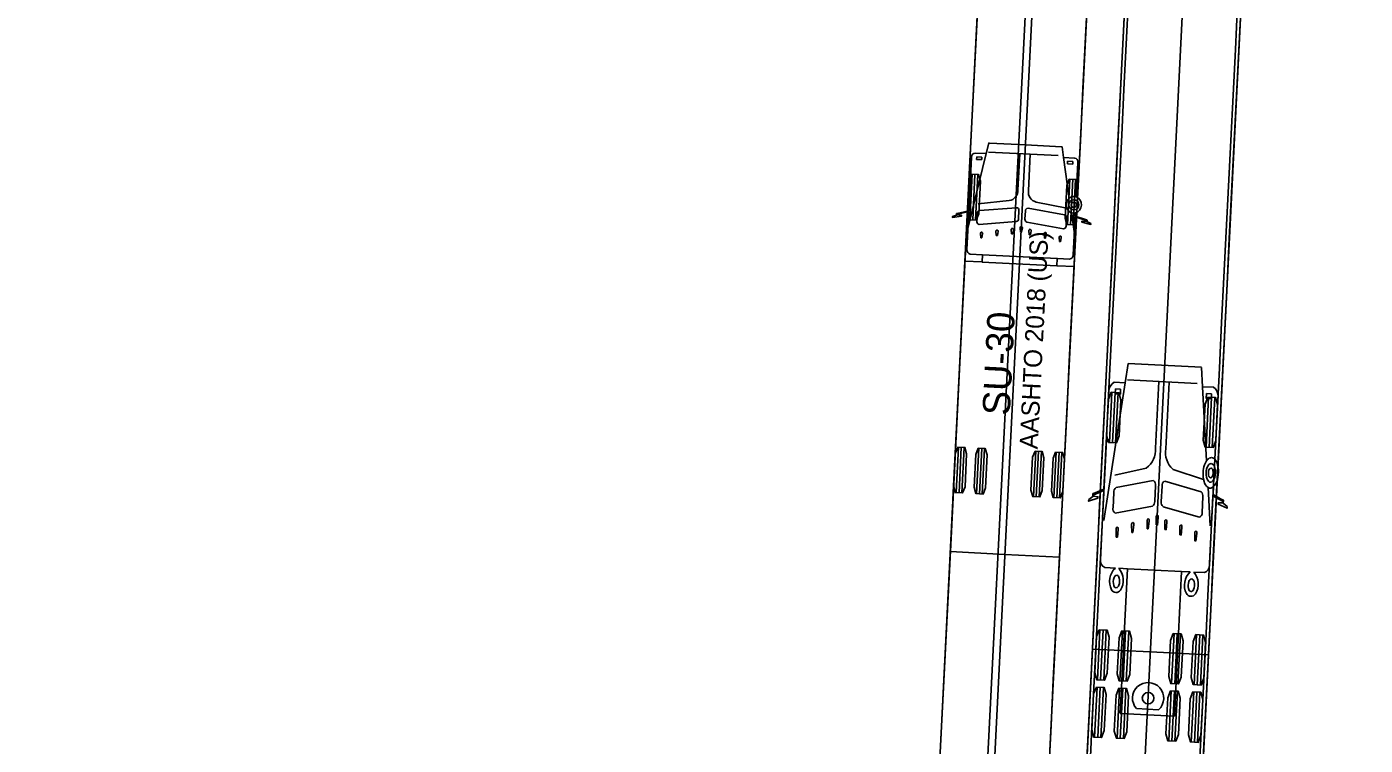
# Model space of a CAD drawing. Extents: x 260275 to 261282, y 610916 to 614143.
# Drawn here: x 260986.2 to 261084.3, y 612318.4 to 612371 of the extents above; entities that cross this region are included whole.
import ezdxf

# ---------------------------------------------------------------- set-up
doc = ezdxf.new("R2010")
doc.units = 0
doc.layers.add('GE_X_Alignment', color=7, linetype='Continuous')
doc.layers.add('TopoDOT_Transients', color=7, linetype='Continuous')

msp = doc.modelspace()

# ---------------------------------------------------------------- linework, layer by layer
at = {"layer": 'GE_X_Alignment'}
msp.add_line((260986.249, 610915.954), (261148.276, 614142.838), dxfattribs=at)
at = {"layer": 'TopoDOT_Transients'}
for p, q in [((261059.045, 612136.423), (261081.046, 612574.591)), ((261048.059, 612136.974), (261068.197, 612538.052)), ((261055.162, 612356.208), (261056.503, 612361.676)), ((261061.757, 612361.535), (261056.658, 612361.791)), ((261058.958, 612361.676), (261058.824, 612359.011)), ((261059.723, 612361.637), (261059.589, 612358.972)), ((261055.791, 612361.255), (261055.801, 612361.449)), ((261056.17, 612361.236), (261055.791, 612361.255)), ((261055.801, 612361.449), (261056.179, 612361.43)), ((261056.179, 612361.43), (261056.17, 612361.236)), ((261062.584, 612358.426), (261062.166, 612361.391)), ((261062.463, 612361.115), (261062.453, 612360.921)), ((261062.453, 612360.921), (261062.831, 612360.902)), ((261062.841, 612361.096), (261062.463, 612361.115)), ((261062.831, 612360.902), (261062.841, 612361.096)), ((261063.088, 612358.516), (261063.214, 612361.035)), ((261055.469, 612360.17), (261055.302, 612356.841)), ((261055.677, 612360.16), (261055.51, 612356.831)), ((261055.885, 612360.15), (261055.718, 612356.82)), ((261062.627, 612359.811), (261062.46, 612356.482)), ((261062.835, 612359.801), (261062.668, 612356.472)), ((261063.043, 612359.79), (261062.876, 612356.461)), ((261058.186, 612358.235), (261055.907, 612358.004)), ((261056.014, 612357.505), (261058.723, 612357.721)), ((261062.234, 612357.192), (261059.561, 612357.679)), ((261060.146, 612358.136), (261062.402, 612357.676)), ((261055.822, 612356.695), (261055.853, 612357.311)), ((261058.702, 612356.7), (261055.993, 612356.484)), ((261058.894, 612357.51), (261058.863, 612356.894)), ((261059.369, 612357.486), (261059.338, 612356.87)), ((261059.479, 612356.661), (261062.153, 612356.174)), ((261062.344, 612356.367), (261062.375, 612356.983)), ((261062.952, 612355.817), (261062.736, 612357.351)), ((261056.105, 612355.524), (261056.084, 612355.825)), ((261056.238, 612355.818), (261056.187, 612355.52)), ((261057.231, 612355.678), (261057.21, 612355.993)), ((261057.314, 612355.674), (261057.231, 612355.678)), ((261057.364, 612355.986), (261057.314, 612355.674)), ((261058.356, 612355.804), (261058.335, 612356.106)), ((261058.439, 612355.8), (261058.356, 612355.804)), ((261058.49, 612356.098), (261058.439, 612355.8)), ((261059.012, 612355.94), (261058.991, 612356.241)), ((261059.094, 612355.936), (261059.012, 612355.94)), ((261059.145, 612356.233), (261059.094, 612355.936)), ((261059.651, 612355.739), (261059.63, 612356.041)), ((261059.733, 612355.735), (261059.651, 612355.739)), ((261059.784, 612356.033), (261059.733, 612355.735)), ((261060.758, 612355.501), (261060.737, 612355.802)), ((261060.891, 612355.795), (261060.84, 612355.497)), ((261056.187, 612355.52), (261056.105, 612355.524)), ((261060.84, 612355.497), (261060.758, 612355.501)), ((261061.863, 612355.235), (261061.842, 612355.536)), ((261061.945, 612355.231), (261061.863, 612355.235)), ((261061.996, 612355.529), (261061.945, 612355.231)), ((261061.679, 612353.471), (261056.194, 612353.746)), ((261061.705, 612354.001), (261056.22, 612354.277)), ((261072.259, 612346.049), (261066.895, 612346.318)), ((261065.102, 612334.832), (261066.674, 612344.901)), ((261071.934, 612344.862), (261066.835, 612345.118)), ((261069.135, 612345.003), (261068.889, 612340.117)), ((261069.899, 612344.964), (261069.654, 612340.079)), ((261065.703, 612344.208), (261065.519, 612340.546)), ((261065.931, 612344.197), (261065.748, 612340.535)), ((261065.944, 612344.101), (261065.962, 612344.456)), ((261066.322, 612344.082), (261065.944, 612344.101)), ((261065.962, 612344.456), (261066.34, 612344.437)), ((261066.16, 612344.185), (261065.976, 612340.523)), ((261066.34, 612344.437), (261066.322, 612344.082)), ((261072.633, 612339.203), (261072.337, 612344.616)), ((261072.624, 612344.122), (261072.606, 612343.766)), ((261073.002, 612344.103), (261072.624, 612344.122)), ((261072.984, 612343.747), (261073.002, 612344.103)), ((261073.237, 612339.306), (261073.473, 612344.001)), ((261072.777, 612343.853), (261072.593, 612340.191)), ((261072.606, 612343.766), (261072.984, 612343.747)), ((261073.006, 612343.842), (261072.822, 612340.18)), ((261073.235, 612343.83), (261073.051, 612340.168)), ((261054.466, 612340.196), (261054.299, 612336.867)), ((261054.674, 612340.185), (261054.507, 612336.856)), ((261054.883, 612340.175), (261054.715, 612336.846)), ((261055.964, 612340.12), (261055.797, 612336.791)), ((261056.173, 612340.11), (261056.005, 612336.781)), ((261056.381, 612340.1), (261056.213, 612336.77)), ((261060.126, 612339.911), (261059.959, 612336.582)), ((261060.334, 612339.901), (261060.167, 612336.572)), ((261060.542, 612339.891), (261060.375, 612336.561)), ((261061.624, 612339.836), (261061.457, 612336.507)), ((261061.832, 612339.826), (261061.665, 612336.497)), ((261062.04, 612339.815), (261061.873, 612336.486)), ((261068.217, 612338.67), (261065.924, 612338.151)), ((261070.178, 612338.571), (261072.419, 612337.822)), ((261066.011, 612337.242), (261068.734, 612337.751)), ((261068.897, 612337.372), (261068.84, 612336.243)), ((261069.372, 612337.348), (261069.315, 612336.219)), ((261072.23, 612336.93), (261069.572, 612337.709)), ((261072.893, 612334.441), (261072.74, 612337.241)), ((261064.33, 612336.6), (261064.309, 612336.585)), ((261064.356, 612336.598), (261064.33, 612336.6)), ((261065.784, 612335.751), (261065.841, 612336.88)), ((261072.307, 612335.423), (261072.363, 612336.552)), ((261073.812, 612336.123), (261073.838, 612336.123)), ((261073.838, 612336.123), (261073.858, 612336.105)), ((261068.67, 612335.88), (261065.947, 612335.372)), ((261068.949, 612334.502), (261068.941, 612335.053)), ((261069.448, 612335.841), (261072.107, 612335.062)), ((261066.019, 612333.619), (261066.011, 612334.17)), ((261066.165, 612334.162), (261066.101, 612333.615)), ((261067.154, 612333.948), (261067.146, 612334.524)), ((261067.3, 612334.517), (261067.236, 612333.944)), ((261068.287, 612334.226), (261068.278, 612334.777)), ((261068.369, 612334.222), (261068.287, 612334.226)), ((261068.432, 612334.769), (261068.369, 612334.222)), ((261069.032, 612334.498), (261068.949, 612334.502)), ((261069.095, 612335.045), (261069.032, 612334.498)), ((261069.581, 612334.161), (261069.573, 612334.712)), ((261069.664, 612334.157), (261069.581, 612334.161)), ((261069.727, 612334.704), (261069.664, 612334.157)), ((261070.68, 612333.771), (261070.672, 612334.322)), ((261070.826, 612334.314), (261070.763, 612333.767)), ((261066.101, 612333.615), (261066.019, 612333.619)), ((261067.236, 612333.944), (261067.154, 612333.948)), ((261070.763, 612333.767), (261070.68, 612333.771)), ((261071.777, 612333.33), (261071.769, 612333.881)), ((261071.859, 612333.326), (261071.777, 612333.33)), ((261071.923, 612333.873), (261071.859, 612333.326)), ((261065.18, 612331.385), (261065.954, 612331.346)), ((261070.809, 612331.103), (261066.841, 612331.302)), ((261071.696, 612331.058), (261072.471, 612331.019)), ((261064.83, 612326.83), (261064.646, 612323.168)), ((261065.059, 612326.819), (261064.875, 612323.157)), ((261065.288, 612326.807), (261065.104, 612323.145)), ((261066.478, 612326.748), (261066.294, 612323.086)), ((261066.707, 612326.736), (261066.523, 612323.074)), ((261066.936, 612326.725), (261066.752, 612323.063)), ((261070.256, 612326.558), (261070.073, 612322.896)), ((261070.485, 612326.546), (261070.301, 612322.884)), ((261070.714, 612326.535), (261070.53, 612322.873)), ((261071.904, 612326.475), (261071.721, 612322.813)), ((261072.133, 612326.464), (261071.949, 612322.802)), ((261072.362, 612326.452), (261072.178, 612322.79)), ((261064.619, 612322.636), (261064.435, 612318.974)), ((261064.848, 612322.624), (261064.664, 612318.962)), ((261065.077, 612322.613), (261064.893, 612318.951)), ((261066.267, 612322.553), (261066.083, 612318.891)), ((261066.496, 612322.541), (261066.312, 612318.879)), ((261066.725, 612322.53), (261066.541, 612318.868)), ((261070.046, 612322.363), (261069.862, 612318.701)), ((261070.275, 612322.352), (261070.091, 612318.69)), ((261070.504, 612322.34), (261070.32, 612318.678)), ((261071.694, 612322.28), (261071.51, 612318.618)), ((261071.923, 612322.269), (261071.739, 612318.607)), ((261072.152, 612322.257), (261071.968, 612318.595)), ((261067.507, 612321.059), (261069.121, 612320.978))]:
    msp.add_line(p, q, dxfattribs=at)
for points in [[(261051.548, 612071.863), (261074.206, 612523.277)], [(261082.631, 612521.243), (261060.03, 612071.291)], [(261042.767, 612111.356), (261063.016, 612514.614)], [(261070.923, 612512.551), (261050.75, 612110.806), (261042.76, 612111.207), (261042.767, 612111.356), (261042.767, 612111.356)], [(261053.088, 612316.907), (261053.256, 612320.235), (261053.423, 612323.564), (261053.59, 612326.892), (261053.757, 612330.22), (261053.924, 612333.549), (261054.091, 612336.877), (261054.258, 612340.206), (261054.425, 612343.534), (261054.593, 612346.863), (261054.76, 612350.191), (261054.927, 612353.52), (261055.094, 612356.848), (261055.261, 612360.176), (261055.428, 612363.505), (261055.595, 612366.833), (261055.762, 612370.162), (261055.93, 612373.49)], [(261053.089, 612316.911), (261053.256, 612320.239), (261053.423, 612323.568), (261053.59, 612326.896), (261053.757, 612330.225), (261053.924, 612333.553), (261054.091, 612336.881), (261054.258, 612340.21), (261054.426, 612343.538), (261054.593, 612346.867), (261054.76, 612350.195), (261054.927, 612353.524), (261055.094, 612356.852), (261055.261, 612360.181), (261055.428, 612363.509), (261055.596, 612366.837), (261055.763, 612370.166), (261055.93, 612373.494)], [(261061.078, 612316.505), (261061.245, 612319.834), (261061.413, 612323.162), (261061.58, 612326.491), (261061.747, 612329.819), (261061.914, 612333.148), (261062.081, 612336.476), (261062.248, 612339.805), (261062.415, 612343.133), (261062.582, 612346.461), (261062.75, 612349.79), (261062.917, 612353.118), (261063.084, 612356.447), (261063.251, 612359.775), (261063.418, 612363.104), (261063.585, 612366.432), (261063.752, 612369.761), (261063.919, 612373.089)], [(261061.079, 612316.51), (261061.246, 612319.838), (261061.413, 612323.166), (261061.58, 612326.495), (261061.747, 612329.823), (261061.914, 612333.152), (261062.081, 612336.48), (261062.248, 612339.809), (261062.416, 612343.137), (261062.583, 612346.466), (261062.75, 612349.794), (261062.917, 612353.123), (261063.084, 612356.451), (261063.251, 612359.779), (261063.418, 612363.108), (261063.585, 612366.436), (261063.753, 612369.765), (261063.92, 612373.093)], [(261063.803, 612315.939), (261063.971, 612319.268), (261064.138, 612322.598), (261064.305, 612325.928), (261064.472, 612329.257), (261064.639, 612332.587), (261064.806, 612335.916), (261064.974, 612339.246), (261065.141, 612342.575), (261065.308, 612345.905), (261065.475, 612349.234), (261065.642, 612352.564), (261065.81, 612355.893), (261065.977, 612359.223), (261066.144, 612362.553), (261066.311, 612365.882), (261066.478, 612369.212), (261066.645, 612372.541)], [(261064.078, 612316.418), (261064.245, 612319.748), (261064.412, 612323.078), (261064.579, 612326.407), (261064.746, 612329.737), (261064.914, 612333.066), (261065.081, 612336.396), (261065.248, 612339.725), (261065.415, 612343.055), (261065.582, 612346.384), (261065.75, 612349.714), (261065.917, 612353.043), (261066.084, 612356.373), (261066.251, 612359.703), (261066.418, 612363.032), (261066.585, 612366.362), (261066.753, 612369.691), (261066.92, 612373.021)], [(261072.068, 612316.017), (261072.235, 612319.347), (261072.402, 612322.676), (261072.569, 612326.006), (261072.736, 612329.335), (261072.904, 612332.665), (261073.071, 612335.995), (261073.238, 612339.324), (261073.405, 612342.654), (261073.572, 612345.983), (261073.739, 612349.313), (261073.907, 612352.642), (261074.074, 612355.972), (261074.241, 612359.301), (261074.408, 612362.631), (261074.575, 612365.96), (261074.743, 612369.29), (261074.91, 612372.62)], [(261072.293, 612315.513), (261072.46, 612318.842), (261072.627, 612322.172), (261072.794, 612325.501), (261072.961, 612328.831), (261073.129, 612332.16), (261073.296, 612335.49), (261073.463, 612338.819), (261073.63, 612342.149), (261073.797, 612345.479), (261073.964, 612348.808), (261074.132, 612352.138), (261074.299, 612355.467), (261074.466, 612358.797), (261074.633, 612362.126), (261074.8, 612365.456), (261074.968, 612368.785), (261075.135, 612372.115)], [(261062.976, 612361.351), (261062.17, 612361.391), (261062.165, 612361.396), (261062.056, 612362.174), (261062.014, 612362.178), (261059.373, 612362.311), (261056.733, 612362.443), (261056.691, 612362.443), (261056.504, 612361.68), (261056.499, 612361.676), (261055.692, 612361.716)], [(261055.424, 612361.426), (261055.227, 612357.498), (261055.219, 612357.487), (261054.378, 612357.302), (261054.377, 612357.303)], [(261054.333, 612357.232), (261054.329, 612357.185), (261054.329, 612357.184), (261054.028, 612357.067), (261054.025, 612357.003), (261054.028, 612357.003), (261054.69, 612357.109), (261054.693, 612357.11), (261054.696, 612357.165), (261054.693, 612357.166), (261054.376, 612357.19), (261054.376, 612357.191), (261054.379, 612357.235)], [(261054.391, 612357.254), (261054.391, 612357.254), (261055.219, 612357.433), (261055.223, 612357.42), (261055.084, 612354.65)], [(261062.874, 612354.259), (261063.013, 612357.029), (261063.018, 612357.041), (261063.824, 612356.781), (261063.824, 612356.781)], [(261063.843, 612356.827), (261063.842, 612356.827), (261063.023, 612357.095), (261063.017, 612357.107), (261063.028, 612357.335)], [(261063.834, 612356.76), (261063.832, 612356.716), (261063.832, 612356.715), (261063.514, 612356.723), (261063.512, 612356.723), (261063.509, 612356.667), (261063.512, 612356.666), (261064.16, 612356.494), (261064.163, 612356.493), (261064.166, 612356.558), (261063.878, 612356.705), (261063.878, 612356.705), (261063.88, 612356.752)], [(261055.322, 612354.322), (261056.217, 612354.277), (261056.22, 612354.273), (261056.194, 612353.747), (261056.183, 612353.747), (261054.941, 612353.809), (261053.874, 612332.549), (261057.869, 612332.348), (261061.864, 612332.148), (261062.931, 612353.408), (261061.69, 612353.47), (261061.679, 612353.471), (261061.705, 612353.998), (261061.709, 612354.001), (261062.604, 612353.956)], [(261072.259, 612346.049), (261066.895, 612346.318), (261066.674, 612344.901), (261065.86, 612344.942)], [(261073.151, 612344.575), (261072.337, 612344.616), (261072.26, 612346.037)], [(261065.483, 612344.402), (261065.118, 612337.134), (261064.361, 612336.803)], [(261064.374, 612336.716), (261064.374, 612336.716), (261065.113, 612337.035), (261064.858, 612331.96)], [(261073.827, 612336.328), (261073.108, 612336.733), (261073.137, 612337.306)], [(261064.314, 612336.672), (261064.309, 612336.585), (261064.002, 612336.359), (261063.996, 612336.239), (261064.67, 612336.463), (261064.675, 612336.566), (261064.356, 612336.598), (261064.361, 612336.68)], [(261072.848, 612331.559), (261073.103, 612336.634), (261073.806, 612336.242), (261073.806, 612336.242)], [(261073.816, 612336.205), (261073.812, 612336.123), (261073.491, 612336.123), (261073.486, 612336.02), (261074.134, 612335.73), (261074.14, 612335.85), (261073.858, 612336.105), (261073.861, 612336.192)], [(261066.211, 612331.333), (261066.841, 612331.302), (261066.309, 612320.715), (261070.278, 612320.516), (261070.809, 612331.103), (261071.439, 612331.071)], [(261070.343, 612277.129), (261070.365, 612277.127), (261072.769, 612324.997), (261068.524, 612325.21), (261064.28, 612325.423), (261061.876, 612277.554), (261061.898, 612277.553)]]:
    msp.add_lwpolyline(points, dxfattribs=at)
for points in [[(261055.418, 612360.173), (261055.937, 612360.147), (261056.07, 612359.673), (261055.95, 612357.276), (261055.77, 612356.818), (261055.251, 612356.844), (261055.118, 612357.318), (261055.238, 612359.715)], [(261062.575, 612359.814), (261063.095, 612359.788), (261063.228, 612359.314), (261063.107, 612356.917), (261062.928, 612356.458), (261062.408, 612356.485), (261062.275, 612356.958), (261062.396, 612359.355)], [(261065.646, 612344.211), (261066.217, 612344.183), (261066.363, 612343.661), (261066.231, 612341.025), (261066.033, 612340.521), (261065.462, 612340.549), (261065.316, 612341.071), (261065.448, 612343.707)], [(261072.72, 612343.856), (261073.292, 612343.827), (261073.438, 612343.306), (261073.306, 612340.669), (261073.108, 612340.165), (261072.536, 612340.194), (261072.39, 612340.715), (261072.522, 612343.352)], [(261054.415, 612340.198), (261054.934, 612340.172), (261055.067, 612339.698), (261054.947, 612337.301), (261054.767, 612336.843), (261054.248, 612336.869), (261054.115, 612337.343), (261054.235, 612339.74)], [(261055.913, 612340.123), (261056.432, 612340.097), (261056.565, 612339.623), (261056.445, 612337.226), (261056.265, 612336.768), (261055.746, 612336.794), (261055.613, 612337.268), (261055.733, 612339.665)], [(261060.074, 612339.914), (261060.594, 612339.888), (261060.727, 612339.414), (261060.606, 612337.017), (261060.426, 612336.559), (261059.907, 612336.585), (261059.774, 612337.059), (261059.894, 612339.456)], [(261061.572, 612339.839), (261062.092, 612339.813), (261062.225, 612339.339), (261062.104, 612336.942), (261061.925, 612336.484), (261061.405, 612336.51), (261061.272, 612336.984), (261061.393, 612339.381)], [(261064.773, 612326.833), (261065.345, 612326.805), (261065.491, 612326.283), (261065.359, 612323.647), (261065.161, 612323.142), (261064.589, 612323.171), (261064.443, 612323.692), (261064.575, 612326.329)], [(261066.421, 612326.75), (261066.992, 612326.722), (261067.139, 612326.2), (261067.006, 612323.564), (261066.809, 612323.06), (261066.237, 612323.088), (261066.091, 612323.61), (261066.223, 612326.246)], [(261070.2, 612326.561), (261070.771, 612326.532), (261070.917, 612326.011), (261070.785, 612323.374), (261070.587, 612322.87), (261070.016, 612322.899), (261069.869, 612323.42), (261070.002, 612326.057)], [(261071.848, 612326.478), (261072.419, 612326.449), (261072.565, 612325.928), (261072.433, 612323.291), (261072.235, 612322.787), (261071.664, 612322.816), (261071.517, 612323.337), (261071.65, 612325.974)], [(261064.563, 612322.638), (261065.134, 612322.61), (261065.28, 612322.088), (261065.148, 612319.452), (261064.95, 612318.948), (261064.379, 612318.976), (261064.232, 612319.498), (261064.365, 612322.134)], [(261066.211, 612322.556), (261066.782, 612322.527), (261066.928, 612322.006), (261066.796, 612319.369), (261066.598, 612318.865), (261066.027, 612318.894), (261065.88, 612319.415), (261066.013, 612322.052)], [(261069.989, 612322.366), (261070.56, 612322.337), (261070.707, 612321.816), (261070.574, 612319.179), (261070.377, 612318.675), (261069.805, 612318.704), (261069.659, 612319.225), (261069.791, 612321.862)], [(261071.637, 612322.283), (261072.208, 612322.255), (261072.355, 612321.733), (261072.222, 612319.097), (261072.024, 612318.593), (261071.453, 612318.621), (261071.307, 612319.143), (261071.439, 612321.779)]]:
    msp.add_lwpolyline(points, close=True, dxfattribs=at)
for centre, radius in [((261062.913, 612357.933), 0.374), ((261062.913, 612357.933), 0.193), ((261068.354, 612321.826), 0.424)]:
    msp.add_circle(centre, radius, dxfattribs=at)
for centre, radius, start, end in [((261055.705, 612361.435), 0.282, 92.67391, 181.75333), ((261062.935, 612361.072), 0.282, 352.49767, 81.5771), ((261058.051, 612358.996), 0.773, 280.01597, 1.10013), ((261060.356, 612358.88), 0.773, 173.15088, 254.23504), ((261058.712, 612357.537), 0.184, 351.66723, 86.52737), ((261059.553, 612357.494), 0.184, 87.72364, 182.58377), ((261062.982, 612357.922), 0.63, 176.4803, 228.88311), ((261062.982, 612357.938), 0.629, 129.17109, 177.86038), ((261062.917, 612358.019), 0.526, 71.07067, 129.31667), ((261062.846, 612357.936), 0.628, 286.8788, 67.3705), ((261054.355, 612357.266), 0.0418, 59.61742, 236.63235), ((261054.35, 612357.267), 0.0434, 312.53921, 343.21198), ((261056.004, 612356.668), 0.184, 171.66167, 266.53293), ((261056.045, 612357.314), 0.193, 99.26792, 181.18241), ((261058.671, 612356.89), 0.193, 279.26299, 1.18734), ((261059.529, 612356.847), 0.193, 173.06366, 254.98801), ((261062.184, 612357.006), 0.193, 353.06859, 74.98308), ((261062.909, 612357.846), 0.524, 229.38452, 283.18459), ((261063.866, 612356.789), 0.0434, 191.03902, 221.7118), ((261063.86, 612356.789), 0.0418, 297.61865, 114.63358), ((261056.174, 612355.839), 0.091, 94.64508, 188.80895), ((261056.15, 612355.841), 0.0909, 345.40639, 79.64159), ((261057.3, 612355.993), 0.091, 94.64508, 188.80895), ((261057.277, 612355.995), 0.0909, 345.40639, 79.64159), ((261058.425, 612356.12), 0.091, 94.64508, 188.80895), ((261058.402, 612356.121), 0.0909, 345.40639, 79.64159), ((261059.081, 612356.255), 0.091, 94.64508, 188.80895), ((261059.057, 612356.256), 0.091, 345.44206, 79.60593), ((261059.72, 612356.055), 0.0909, 94.60942, 188.84462), ((261059.696, 612356.056), 0.091, 345.44206, 79.60593), ((261060.827, 612355.816), 0.0909, 94.60942, 188.84462), ((261060.803, 612355.818), 0.091, 345.44206, 79.60593), ((261061.932, 612355.55), 0.0909, 94.60942, 188.84462), ((261061.908, 612355.551), 0.091, 345.44206, 79.60593), ((261062.16, 612356.359), 0.184, 267.71808, 2.58934), ((261055.406, 612354.634), 0.323, 177.1255, 254.97391), ((261062.552, 612354.275), 0.323, 279.2771, 357.1255), ((261066.261, 612344.259), 0.792, 120.43659, 169.59206), ((261072.684, 612343.937), 0.792, 4.65895, 53.81442), ((261067.263, 612339.992), 1.631, 305.80134, 4.39207), ((261071.259, 612339.792), 1.631, 169.85894, 228.44967), ((261073.511, 612338.584), 1.074, 138.58211, 162.85096), ((261073.001, 612339.055), 0.38, 90.45588, 140.97941), ((261072.986, 612338.732), 0.268, 92.19814, 155.87577), ((261072.845, 612338.614), 0.407, 8.35614, 71.16055), ((261072.976, 612339.108), 0.328, 37.21385, 86.11819), ((261072.719, 612338.808), 0.719, 15.6559, 43.91288), ((261071.772, 612338.446), 1.731, 3.5106, 18.70836), ((261074.39, 612338.229), 2.012, 176.76687, 195.44978), ((261074.429, 612338.251), 2.049, 161.50654, 177.43184), ((261073.509, 612338.235), 0.914, 173.95993, 216.01791), ((261073.697, 612338.299), 1.098, 150.39127, 178.28386), ((261073.381, 612338.293), 0.617, 169.4131, 202.60389), ((261073.044, 612338.411), 0.27, 108.27444, 181.01824), ((261072.929, 612338.081), 0.12, 192.10162, 337.57965), ((261072.884, 612338.461), 0.22, 8.13535, 69.83363), ((261072.488, 612338.342), 0.631, 330.93378, 13.73431), ((261072.371, 612338.286), 0.913, 320.43513, 0.69541), ((261072.052, 612338.367), 1.234, 356.75519, 14.33734), ((261071.301, 612338.4), 2.204, 344.32456, 3.95974), ((261066.243, 612336.912), 0.403, 125.12521, 184.58316), ((261068.563, 612337.458), 0.342, 348.72731, 58.65379), ((261069.713, 612337.401), 0.342, 115.59721, 185.52369), ((261073.23, 612337.872), 0.799, 192.92493, 232.19257), ((261072.902, 612337.494), 0.301, 237.35677, 321.25506), ((261072.919, 612337.828), 0.199, 220.92879, 321.5681), ((261072.518, 612337.992), 0.924, 312.02262, 348.30076), ((261064.425, 612336.734), 0.127, 145.02093, 209.23008), ((261064.34, 612336.792), 0.0244, 27.99309, 141.30746), ((261064.265, 612336.734), 0.11, 330.07302, 350.18134), ((261068.443, 612336.206), 0.397, 304.88665, 3.04966), ((261069.707, 612336.143), 0.397, 171.20134, 229.36435), ((261071.966, 612336.625), 0.403, 349.66784, 49.12579), ((261073.916, 612336.25), 0.11, 184.06966, 204.17798), ((261073.848, 612336.314), 0.0244, 32.94354, 146.25791), ((261073.757, 612336.265), 0.127, 325.02093, 29.23008), ((261066.109, 612335.663), 0.334, 168.26267, 240.86063), ((261069.131, 612335.085), 0.192, 122.20119, 189.67576), ((261068.91, 612335.096), 0.192, 344.57524, 52.04981), ((261071.974, 612335.368), 0.334, 293.39037, 5.98833), ((261066.2, 612334.202), 0.192, 122.20119, 189.67576), ((261065.98, 612334.213), 0.192, 344.5479, 52.07716), ((261067.335, 612334.531), 0.192, 122.20119, 189.67576), ((261067.115, 612334.543), 0.192, 344.5479, 52.07716), ((261068.468, 612334.809), 0.192, 122.20119, 189.67576), ((261068.247, 612334.82), 0.192, 344.5479, 52.07716), ((261069.762, 612334.744), 0.192, 122.17384, 189.70311), ((261069.542, 612334.755), 0.192, 344.57524, 52.04981), ((261070.862, 612334.354), 0.192, 122.17384, 189.70311), ((261070.641, 612334.365), 0.192, 344.57524, 52.04981), ((261071.958, 612333.913), 0.192, 122.17384, 189.70311), ((261071.737, 612333.924), 0.192, 344.57524, 52.04981), ((261065.426, 612331.9), 0.571, 174.04089, 244.43248), ((261066.873, 612330.366), 1.344, 133.16094, 206.71574), ((261065.199, 612330.45), 1.344, 327.53526, 41.09006), ((261072.277, 612331.556), 0.571, 289.81853, 0.21012), ((261066.658, 612330.337), 0.86, 158.69148, 198.66086), ((261066.131, 612330.555), 0.29, 104.76976, 160.92979), ((261065.995, 612330.596), 0.247, 5.52911, 75.4082), ((261065.39, 612330.399), 0.879, 339.9934, 14.58864), ((261072.358, 612330.091), 1.344, 133.16094, 206.71574), ((261072.162, 612330.059), 0.879, 159.66236, 194.25761), ((261071.58, 612330.316), 0.247, 98.8428, 168.7219), ((261071.441, 612330.288), 0.29, 13.32121, 69.48124), ((261070.895, 612330.125), 0.86, 335.59014, 15.55953), ((261070.684, 612330.175), 1.344, 327.53526, 41.09006), ((261066.013, 612329.948), 0.387, 208.62104, 325.62996), ((261066.064, 612330.119), 0.228, 194.4278, 256.32264), ((261065.961, 612330.155), 0.262, 280.91747, 347.44267), ((261071.497, 612329.664), 0.383, 207.59628, 326.65472), ((261071.57, 612329.873), 0.262, 186.80834, 253.33353), ((261071.464, 612329.848), 0.228, 277.92836, 339.8232), ((261068.354, 612321.826), 1.143, 312.1255, 222.1255)]:
    msp.add_arc(centre, radius, start, end, dxfattribs=at)
for centre, major_axis, start_param, end_param in [((261064.337, 612336.738), (-0.0039, -0.0781), 5.756759, 7.026061), ((261064.337, 612336.738), (0.0039, 0.0781), 4.442794, 5.713538), ((261073.845, 612336.261), (-0.0039, -0.0781), 3.71124, 4.981984), ((261073.845, 612336.261), (0.0039, 0.0781), 2.398717, 3.668019)]:
    msp.add_ellipse(centre, major_axis=major_axis, ratio=0.5, start_param=start_param, end_param=end_param, dxfattribs=at)

# ---------------------------------------------------------------- texts
for s, height, p in [('AASHTO 2018 (US)', 1.33333, (261060.263, 612340.024)), ('SU-30', 2, (261058.218, 612342.487))]:
    msp.add_text(s, height=height, rotation=87.1255, dxfattribs=at).set_placement(p)

doc.saveas('drawing.dxf')
